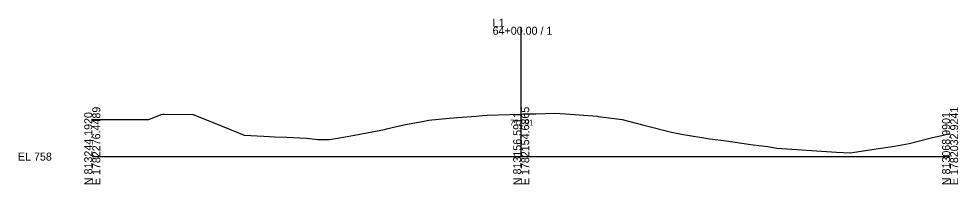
# Model space of a CAD drawing. Extents: x 5574 to 10203, y -10 to 9546.
# Drawn here: x 7574.3 to 7902.8, y 1490.3 to 1548.3 of the extents above; entities that cross this region are included whole.
import ezdxf

# ---------------------------------------------------------------- set-up
doc = ezdxf.new("R2010")
doc.units = 0
for name, color, linetype in [('Exist Cross Section Cell', 7, 'Continuous'), ('Exist XS Center Line Elevation Label', 7, 'Continuous'), ('Exist XS Ground Line', 7, 'Continuous')]:
    doc.layers.add(name, color=color, linetype=linetype)

msp = doc.modelspace()

# ---------------------------------------------------------------- linework, layer by layer
at = {"layer": 'Exist Cross Section Cell'}
for p, q in [((7750, 1500), (7750, 1545.52)), ((7600, 1500), (7750, 1500)), ((7750, 1500), (7900, 1500))]:
    msp.add_line(p, q, dxfattribs=at)
at = {"layer": 'Exist XS Ground Line'}
for p, q in [((7619.76, 1513.03), (7624.14, 1514.74)), ((7624.14, 1514.74), (7624.6, 1514.93)), ((7624.6, 1514.93), (7625.18, 1514.92)), ((7625.18, 1514.92), (7635.29, 1514.75)), ((7635.29, 1514.75), (7645.98, 1510.4)), ((7738.16, 1514.49), (7745.96, 1514.77)), ((7745.96, 1514.77), (7750, 1514.91)), ((7750, 1514.91), (7750.68, 1514.94)), ((7750.68, 1514.94), (7755.15, 1515.03)), ((7755.15, 1515.03), (7761.78, 1515.17)), ((7761.78, 1515.17), (7763.58, 1515.11)), ((7763.58, 1515.11), (7765.47, 1515.04)), ((7765.47, 1515.04), (7776.66, 1514.14)), ((7600, 1513.03), (7603.04, 1513.03)), ((7603.04, 1513.03), (7610.69, 1513.03)), ((7610.69, 1513.03), (7618.65, 1513.03)), ((7618.65, 1513.03), (7619.76, 1513.03)), ((7708.93, 1511.1), (7716.01, 1512.42)), ((7716.01, 1512.42), (7717.76, 1512.75)), ((7717.76, 1512.75), (7718.72, 1512.86)), ((7718.72, 1512.86), (7724.94, 1513.52)), ((7724.94, 1513.52), (7727.73, 1513.74)), ((7727.73, 1513.74), (7734.21, 1514.23)), ((7734.21, 1514.23), (7736.46, 1514.37)), ((7736.46, 1514.37), (7738.16, 1514.49)), ((7776.66, 1514.14), (7776.97, 1514.11)), ((7776.97, 1514.11), (7785.36, 1513.05)), ((7785.36, 1513.05), (7792.84, 1511)), ((7645.98, 1510.4), (7653.15, 1507.46)), ((7691.76, 1507.5), (7702.22, 1509.54)), ((7702.22, 1509.54), (7702.63, 1509.61)), ((7702.63, 1509.61), (7702.95, 1509.69)), ((7702.95, 1509.69), (7708.93, 1511.1)), ((7792.84, 1511), (7802.61, 1508.51)), ((7802.61, 1508.51), (7806.03, 1507.9)), ((7895.65, 1507.06), (7900, 1508.06)), ((7653.15, 1507.46), (7660.04, 1507.19)), ((7660.04, 1507.19), (7663.77, 1506.97)), ((7663.77, 1506.97), (7668.06, 1506.82)), ((7668.06, 1506.82), (7674.93, 1506.43)), ((7674.93, 1506.43), (7677.94, 1506.14)), ((7677.94, 1506.14), (7678.92, 1506.02)), ((7678.92, 1506.02), (7680.04, 1506.03)), ((7680.04, 1506.03), (7682.95, 1506.01)), ((7682.95, 1506.01), (7687.85, 1506.87)), ((7687.85, 1506.87), (7691.76, 1507.5)), ((7806.03, 1507.9), (7815.93, 1506.25)), ((7815.93, 1506.25), (7821.68, 1505.48)), ((7821.68, 1505.48), (7824.06, 1505.16)), ((7824.06, 1505.16), (7831.14, 1504.12)), ((7885.69, 1504.65), (7893.43, 1506.55)), ((7893.43, 1506.55), (7894.85, 1506.88)), ((7894.85, 1506.88), (7895.65, 1507.06)), ((7831.14, 1504.12), (7833.16, 1503.84)), ((7833.16, 1503.84), (7836.24, 1503.49)), ((7836.24, 1503.49), (7839.43, 1502.96)), ((7839.43, 1502.96), (7860.28, 1501.61)), ((7860.28, 1501.61), (7865.1, 1501.3)), ((7865.1, 1501.3), (7875.02, 1502.84)), ((7875.02, 1502.84), (7879.06, 1503.43)), ((7879.06, 1503.43), (7880.51, 1503.71)), ((7880.51, 1503.71), (7885.69, 1504.65))]:
    msp.add_line(p, q, dxfattribs=at)

# ---------------------------------------------------------------- texts
at = {"layer": 'Exist Cross Section Cell'}
for s, p in [('L1', (7740, 1545.52)), ('64+00.00 / 1', (7740, 1542.72)), ('EL 758', (7574, 1498.6))]:
    msp.add_text(s, height=2.8, dxfattribs=at).set_placement(p)
for s, p in [('N 813244.1920', (7600, 1490)), ('E 1782276.4489', (7602.8, 1490)), ('N 813156.5911', (7750, 1490)), ('E 1782154.6865', (7752.8, 1490)), ('N 813068.9901', (7900, 1490)), ('E 1782032.9241', (7902.8, 1490))]:
    msp.add_text(s, height=2.8, rotation=90, dxfattribs=at).set_placement(p)
at = {"layer": 'Exist XS Center Line Elevation Label'}
msp.add_text('772.91', height=2, dxfattribs=at).set_placement((7746.08, 1510.91))

doc.saveas('drawing.dxf')
